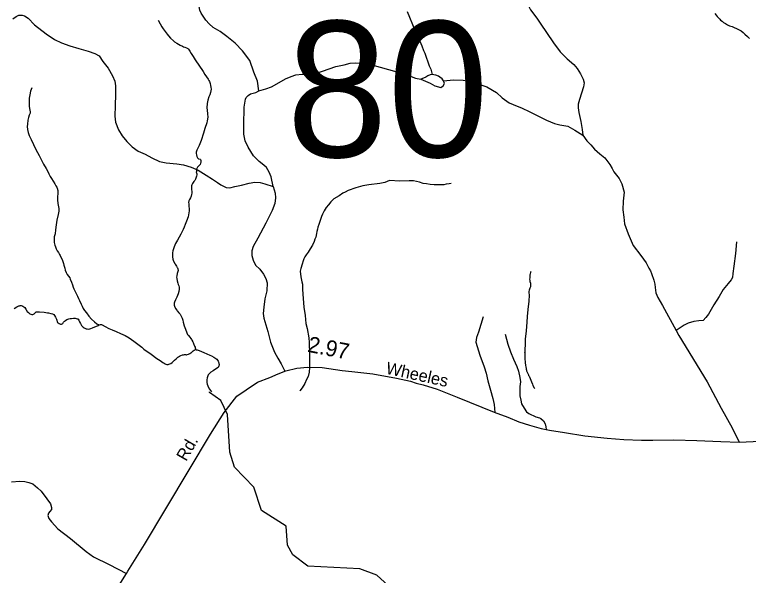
# Model space of a CAD drawing. Extents: x 2220236 to 2384410, y 720751 to 894131.
# Drawn here: x 2300357 to 2306111, y 864576 to 868976 of the extents above; entities that cross this region are included whole.
import ezdxf

# ---------------------------------------------------------------- set-up
doc = ezdxf.new("R2010")
doc.units = 0
doc.layers.add('Default', color=7, linetype='Continuous')

msp = doc.modelspace()

# ---------------------------------------------------------------- linework, layer by layer
at = {"layer": 'Default'}
for points in [[(2302271.3, 868378.4), (2302261.1, 868454.7), (2302233.2, 868525.8), (2302200.2, 868617.3), (2302144.3, 868693.6), (2302085.9, 868752), (2302019.8, 868805.4), (2301969, 868843.5), (2301913.2, 868876.6), (2301882.7, 868904.5), (2301857.3, 868932.5), (2301819.2, 868988.4), (2301809, 869011.3), (2301801.4, 869057)], [(2304370.5, 869077.3), (2304403.5, 869013.8), (2304451.8, 868947.7), (2304479.7, 868909.6), (2304583.8, 868754.6), (2304634.6, 868683.4), (2304690.5, 868630), (2304743.9, 868584.3), (2304769.3, 868553.8), (2304794.7, 868513.1), (2304815, 868469.9), (2304822.6, 868442), (2304817.5, 868408.9), (2304802.3, 868360.6), (2304787, 868309.8), (2304776.9, 868274.2), (2304776.9, 868246.3), (2304782, 868208.2), (2304797.2, 868137), (2304807.4, 868076), (2304812.4, 868030.2)], [(2303435.3, 869000.6), (2303494.8, 868855.2), (2303511.2, 868823.5), (2303550.1, 868731.8), (2303562.6, 868696.1), (2303572.7, 868674.1), (2303607.8, 868574.5), (2303620.1, 868548.6), (2303630.9, 868505.7)], [(2305848.6, 868984.5), (2305858.7, 868972.7), (2305866.7, 868962.4), (2305873.7, 868954.5), (2305886.8, 868941.1), (2305894.1, 868934), (2305905.3, 868924.6), (2305916.1, 868916), (2305931.3, 868906.7), (2305946.7, 868896.7), (2305964.8, 868888.4), (2305984.7, 868882.6), (2306000.7, 868876.7), (2306018.9, 868868.4), (2306038.7, 868858.6), (2306054.7, 868848.7), (2306070.8, 868836.2), (2306084.7, 868824.5), (2306104.8, 868806.3), (2306120.7, 868790.6)], [(2300343.5, 868942.6), (2300368.9, 868963), (2300389.2, 868973.1), (2300414.6, 868973.1), (2300434.9, 868968.1), (2300462.9, 868947.7), (2300511.1, 868896.9), (2300602.6, 868825.7), (2300668.6, 868782.5), (2300724.5, 868754.6), (2300790.5, 868731.7), (2300859.1, 868711.4), (2300932.8, 868691), (2300986.1, 868670.7), (2301019.1, 868652.9), (2301049.6, 868609.7), (2301090.2, 868556.3), (2301123.3, 868495.3), (2301143.6, 868454.7), (2301148.7, 868416.6), (2301148.7, 868350.5), (2301146.1, 868264.1), (2301143.6, 868180.2), (2301148.7, 868131.9), (2301171.5, 868073.5), (2301199.4, 868025.2), (2301237.5, 867982), (2301278.2, 867938.8), (2301326.4, 867905.7), (2301379.8, 867880.3), (2301433.1, 867852.3), (2301491.5, 867824.4), (2301544.9, 867814.2), (2301628.7, 867806.6), (2301682, 867799), (2301740.4, 867778.6), (2301796.3, 867755.8), (2301859.8, 867717.6), (2301908.1, 867684.6), (2301948.7, 867659.2), (2301974.1, 867641.4), (2302014.8, 867621.1), (2302045.2, 867618.5), (2302083.3, 867628.7), (2302136.7, 867638.9), (2302195.1, 867654.1), (2302240.8, 867661.7), (2302281.4, 867659.2), (2302319.5, 867649), (2302385.6, 867628.7)], [(2301481.5, 868934.2), (2301497.6, 868903.7), (2301511.6, 868879.7), (2301521.5, 868866.3), (2301529.6, 868855.8), (2301537.7, 868843.9), (2301553.6, 868822.4), (2301563.7, 868809.8), (2301579.6, 868792.2), (2301601.7, 868771.9), (2301611.6, 868764.1), (2301629.7, 868751.6), (2301641.6, 868743.9), (2301655.7, 868736.3), (2301673.7, 868728), (2301681.6, 868724.2), (2301691.6, 868720.6), (2301705.6, 868716.1), (2301715.6, 868710.2), (2301719.6, 868706.1), (2301725.7, 868698.2), (2301731.7, 868690.2), (2301741.6, 868671.8), (2301755.6, 868647.8), (2301773.7, 868622.1), (2301835.6, 868530.4), (2301849.6, 868508), (2301861.6, 868487.8), (2301873.7, 868470.3), (2301879.6, 868458.4), (2301883.7, 868451.9), (2301889.7, 868435.8), (2301893.8, 868419.5), (2301896.3, 868408), (2301897.8, 868391.7), (2301895.7, 868377.8), (2301893.6, 868366.1), (2301887.6, 868346.3), (2301879.7, 868330.3), (2301871.7, 868306.2), (2301867.6, 868278.2), (2301865.1, 868246.1), (2301867.5, 868227.2), (2301869.7, 868197.9), (2301871.6, 868171.5), (2301867.6, 868142), (2301863.6, 868126.2), (2301849.6, 868082.2), (2301837.7, 868046.3), (2301819.4, 867989.7), (2301803.6, 867949.7), (2301793.7, 867929.6), (2301787.5, 867918), (2301785.6, 867912.1), (2301781.6, 867897.9), (2301781, 867888.1), (2301781.7, 867875.7), (2301785.6, 867863.7), (2301791.6, 867854.1), (2301794.1, 867850.8), (2301799.5, 867846.2), (2301811.7, 867841.7), (2301814.8, 867838.7), (2301817.7, 867832.2), (2301817.6, 867824), (2301817.2, 867815), (2301815.6, 867809.9), (2301811.5, 867801.5), (2301805.6, 867795.5), (2301797.7, 867787.9), (2301791.6, 867780.3), (2301785.1, 867768.4), (2301783.7, 867763.6), (2301782, 867754.3), (2301781.7, 867743.7), (2301781.6, 867739.7), (2301785.6, 867727.4), (2301785.6, 867721.6), (2301785.7, 867720), (2301783.6, 867707.7), (2301781.6, 867701.9), (2301775, 867686), (2301769.7, 867675.9), (2301763, 867666.7), (2301757.5, 867659.8), (2301751.5, 867650.6), (2301747.6, 867642.2), (2301744.4, 867632.3), (2301743.2, 867618.2), (2301743.6, 867603.5), (2301745.7, 867587.9), (2301745.6, 867575.7), (2301744.4, 867564.1), (2301741.2, 867550.9), (2301736.6, 867539.9), (2301727.2, 867525.7), (2301723.2, 867515.6)], [(2302271.3, 868378.4), (2302327.2, 868393.7), (2302370.3, 868408.9), (2302413.5, 868434.3), (2302482.1, 868472.5), (2302525.3, 868490.3), (2302563.4, 868503), (2302611.6, 868510.6), (2302667.5, 868510.6), (2302700.5, 868513.1), (2302731, 868520.8), (2302771.6, 868533.5), (2302875.8, 868569), (2302941.8, 868581.8), (2302987.5, 868594.5), (2303030.7, 868599.5), (2303076.4, 868594.5), (2303139.9, 868586.8), (2303223.7, 868564), (2303419.3, 868510.6), (2303500.6, 868477.5), (2303543.8, 868469.9)], [(2303630.9, 868505.7), (2303615.2, 868502.9), (2303598.6, 868495.6), (2303582.1, 868485.9), (2303562.8, 868477.5), (2303543.8, 868469.9)], [(2303543.8, 868469.9), (2303614.9, 868439.4), (2303653, 868416.6), (2303698.7, 868403.8), (2303719, 868419.1), (2303729.2, 868436.9), (2303721.6, 868457.2)], [(2303721.6, 868457.2), (2303709.9, 868471.8), (2303692.2, 868486.3), (2303680.1, 868493.6), (2303660.7, 868500.5), (2303645.4, 868504.9), (2303630.9, 868505.7)], [(2303721.6, 868457.2), (2303797.7, 868464.8), (2303874.9, 868461.4), (2303903, 868455.8), (2303997.3, 868430.8), (2304059.3, 868409.6), (2304135.8, 868366.3), (2304180.3, 868324.9), (2304236.7, 868285.4), (2304298.9, 868258.1), (2304331.2, 868246.4), (2304397.3, 868213.1), (2304528, 868147.2), (2304591.5, 868121.7), (2304632.1, 868111.6), (2304695.6, 868101.4), (2304751.5, 868070.9), (2304812.4, 868030.2)], [(2300490.4, 868402.2), (2300481.2, 868375.6), (2300475.4, 868348.2), (2300471.3, 868321.8), (2300469.3, 868310.3), (2300469.4, 868279.9), (2300469.3, 868267.5), (2300469.3, 868257.7), (2300472.4, 868239.8), (2300476.6, 868226.8), (2300479.1, 868213.9), (2300477.4, 868202.2), (2300471.3, 868188.1), (2300466.2, 868168.1), (2300461.2, 868147.5), (2300457.2, 868117.7), (2300455.2, 868098), (2300457.3, 868075.9), (2300463.3, 868051.5), (2300471.3, 868028.1), (2300485.4, 867997.4), (2300505.2, 867958), (2300523.2, 867917.7), (2300549.3, 867872), (2300569.3, 867829.4), (2300583.2, 867802), (2300603.3, 867770), (2300618.8, 867740.4), (2300625.3, 867727.5), (2300635.3, 867707.3), (2300645.4, 867691.3), (2300659.3, 867669.8), (2300671.3, 867649.7), (2300680.6, 867633.7), (2300687.2, 867621.7), (2300691.4, 867613.7), (2300695.3, 867595.7), (2300695.4, 867569.5), (2300693.4, 867549.8), (2300691.8, 867524.3), (2300695.3, 867494), (2300699.2, 867481.8), (2300704.1, 867454.2), (2300703.4, 867433.5), (2300697.2, 867407.9), (2300687.2, 867364), (2300681.3, 867327.8), (2300677.3, 867287.4), (2300673.2, 867256), (2300667.4, 867233.6), (2300667.3, 867219.6), (2300667.3, 867205.8), (2300667.2, 867197.6), (2300667.2, 867187.6), (2300669.2, 867177.8), (2300671.7, 867167.3), (2300677.2, 867153.6), (2300683.2, 867139.8), (2300691.3, 867123.7), (2300699.3, 867109.4), (2300707.5, 867095), (2300713.3, 867085.2), (2300719.3, 867074), (2300729.3, 867055.6), (2300735.3, 867039.5), (2300739.2, 867024), (2300743.2, 867009.4), (2300749.3, 866985.8), (2300753.3, 866971.2), (2300761.3, 866951.9), (2300769.3, 866937.4), (2300779.3, 866923.8), (2300788.2, 866911.2), (2300793.1, 866899.8), (2300803.2, 866877.2), (2300811.3, 866855.5), (2300816.2, 866838.5), (2300821.3, 866825.5), (2300829.2, 866809.4), (2300837.3, 866793.4), (2300849.3, 866767.6), (2300857.7, 866748.2), (2300865.3, 866733.7), (2300879.3, 866705.7), (2300885.3, 866689.5), (2300895.2, 866669.3), (2300905.3, 866655.9), (2300919.2, 866635.9), (2300939.2, 866609.7), (2300959.4, 866587.5), (2300982.7, 866565.4), (2301002.3, 866550.6), (2301018.3, 866541.5)], [(2302385.6, 867628.7), (2302367.8, 867702.4), (2302352.6, 867740.5), (2302332.2, 867776.1), (2302311.9, 867796.4), (2302273.8, 867824.4), (2302230.6, 867867.6), (2302187.5, 867936.2), (2302164.6, 867987), (2302154.4, 868037.9), (2302154.4, 868109), (2302157, 868251.4), (2302167.1, 868312.4), (2302172.2, 868327.6), (2302187.5, 868342.8), (2302207.8, 868355.6), (2302248.4, 868365.7), (2302271.3, 868378.4)], [(2304812.4, 868030.2), (2304844.2, 867987), (2304874.7, 867954), (2304905.1, 867921), (2304945.8, 867885.4), (2304985.1, 867853.7), (2305024.5, 867801.5), (2305042.3, 867768.5), (2305057.5, 867743.1), (2305098.2, 867689.7), (2305118.5, 867649), (2305136.3, 867582.9), (2305128.6, 867511.8), (2305126.1, 867445.7), (2305133.7, 867387.2), (2305141.3, 867333.9), (2305168, 867255.1), (2305208.7, 867166.1), (2305267.1, 867087.3), (2305310.2, 867028.9), (2305331.9, 866986.6), (2305344.1, 866966.7), (2305352.8, 866944), (2305369.2, 866894), (2305377.6, 866862.1), (2305379.8, 866836.2), (2305386.3, 866794.3), (2305392.6, 866774.3), (2305400.7, 866756.5), (2305439.3, 866693), (2305545.6, 866498.3)], [(2303780.1, 867650.2), (2303766, 867647.8), (2303740.1, 867645.9), (2303722, 867642), (2303708, 867642.2), (2303670.1, 867639.8), (2303646.1, 867639.7), (2303616.1, 867644.2), (2303586.1, 867647.8), (2303560, 867651.7), (2303531.9, 867662), (2303508, 867666), (2303483.9, 867672.4), (2303450.1, 867671.8), (2303378, 867669.7), (2303296, 867673.7), (2303259.9, 867659.8), (2303222, 867651.9), (2303135.9, 867640.1), (2303088, 867632.4), (2303033.9, 867617.8), (2302973.8, 867595.7), (2302947.9, 867584), (2302929.9, 867574.3), (2302901.8, 867555.7), (2302859.9, 867530.2), (2302835.8, 867506.4), (2302817.7, 867484.2), (2302799.8, 867463.9), (2302783.8, 867437.6), (2302771.8, 867410.1), (2302763.7, 867391.8), (2302757.8, 867375.9), (2302749.8, 867354.2), (2302741.8, 867330.1), (2302735.7, 867307.8), (2302731.8, 867292), (2302727.7, 867273.9), (2302723.8, 867258.1), (2302717.9, 867231.4), (2302711.8, 867214), (2302705.7, 867195.7), (2302691.6, 867168.1), (2302675.8, 867139.5), (2302659.7, 867113.4), (2302643.8, 867091.5), (2302631.8, 867076.3), (2302625.7, 867059.6), (2302619.7, 867043.7), (2302611.8, 867018), (2302601.8, 866983.8), (2302595.8, 866963.9), (2302601.8, 866920), (2302609.6, 866880.1), (2302613.8, 866862), (2302613.8, 866821.8), (2302615.8, 866783.5), (2302619.8, 866750), (2302625.8, 866682), (2302635.7, 866616), (2302639.8, 866553.8), (2302651.7, 866514), (2302663.6, 866441.5), (2302667.8, 866404.1), (2302667.7, 866376), (2302669.7, 866341.7), (2302669.7, 866308.1), (2302669.6, 866276.1), (2302669.6, 866231.9), (2302669.6, 866208.1), (2302667.7, 866171.8), (2302657.7, 866137.7), (2302645.7, 866113.4), (2302631.8, 866081.7), (2302611.5, 866048), (2302593.7, 866023.5), (2302593.3, 866023.5)], [(2302385.6, 867628.7), (2302400.8, 867575.3), (2302403.4, 867539.7), (2302398.3, 867494), (2302375.4, 867440.6), (2302327.2, 867339), (2302263.7, 867222), (2302228.1, 867156), (2302217.9, 867122.9), (2302217.9, 867087.3), (2302228.1, 867049.2), (2302245.9, 867011.1), (2302278.9, 866978.1), (2302309.4, 866939.9), (2302327.2, 866906.9), (2302337.3, 866871.3), (2302334.8, 866807.8), (2302319.5, 866746.8), (2302311.9, 866680.7), (2302306.8, 866632.4), (2302311.9, 866594.3), (2302343.7, 866490.1), (2302364, 866406.2), (2302394.5, 866327.4), (2302419.9, 866281.7), (2302448, 866236.9), (2302475.7, 866177.6)], [(2301723.2, 867515.6), (2301721.1, 867503.3), (2301721.6, 867491.7), (2301723.5, 867473.8), (2301726, 867451.9), (2301725.6, 867437.8), (2301717.6, 867389.9), (2301704.2, 867354.9), (2301695, 867329.9), (2301685.4, 867309.7), (2301677.5, 867289.8), (2301670.1, 867273.9), (2301660.1, 867254.7), (2301633.4, 867207.6), (2301617.5, 867181.5), (2301607.2, 867154.9), (2301597.4, 867124.1), (2301595.5, 867107.6), (2301595, 867099.4), (2301595.5, 867082.2), (2301596, 867074.8), (2301597.5, 867057.6), (2301599.5, 867049.5), (2301603.6, 867041.5), (2301613.1, 867024.5), (2301616.7, 867019), (2301626.6, 867002.2), (2301629.4, 866997.3), (2301631.8, 866993.4), (2301633.5, 866990.1), (2301635.6, 866982.8), (2301638.8, 866968.1), (2301637.4, 866959.8), (2301631.5, 866945.8), (2301627.5, 866927.4), (2301626.9, 866916.8), (2301627.6, 866905.4), (2301631, 866886.5), (2301635.5, 866869.5), (2301639.4, 866857.5), (2301643.5, 866849.4), (2301646.6, 866837.2), (2301647.6, 866823.4), (2301644.4, 866802.7), (2301639.5, 866786.1), (2301629.6, 866759.4), (2301619.5, 866737.6), (2301611.4, 866720.1), (2301608.9, 866711.8), (2301607.5, 866703.5), (2301607.8, 866696.1), (2301609.5, 866688), (2301619.5, 866669.6), (2301627.6, 866657.5), (2301632.4, 866651.1), (2301645.4, 866636), (2301654, 866626.6), (2301663.5, 866611.4), (2301670.5, 866595.2), (2301675.6, 866579.8), (2301679.4, 866563.6), (2301687.4, 866535.3), (2301691.4, 866521.5), (2301695.9, 866508.7), (2301698.8, 866500.4), (2301703.6, 866487.6), (2301706.5, 866479.5), (2301713.4, 866467.4), (2301719.4, 866457.8), (2301729.5, 866446), (2301737.5, 866435.5), (2301743.4, 866427.6), (2301747.3, 866421.1), (2301753.6, 866410), (2301757.1, 866402.7), (2301760.2, 866394.6), (2301767.6, 866375.3), (2301771.6, 866365.7), (2301773.6, 866359.2), (2301774.8, 866355.8), (2301775.5, 866347.7)], [(2306019.7, 867194), (2306011.2, 867102.5), (2305997.7, 867002.5), (2305990.9, 866944.9), (2305987.5, 866914.4), (2305975.7, 866895.8), (2305953.6, 866867), (2305914.7, 866819.6), (2305882.5, 866763.6), (2305840.2, 866699.3), (2305797.9, 866624.7), (2305777.5, 866599.3), (2305757.2, 866575.6), (2305723.4, 866573.9), (2305682.7, 866568.8), (2305638.7, 866555.2), (2305609.3, 866540.9), (2305575.4, 866518.9), (2305545.6, 866498.3)], [(2304406.3, 866960.2), (2304402.1, 866954.4), (2304400.1, 866940.3), (2304398.1, 866933.6), (2304396.2, 866923.7), (2304396.2, 866912.3), (2304396.1, 866899.9), (2304398.1, 866890.2), (2304398.2, 866883.6), (2304402.2, 866869.8), (2304402.2, 866858.4), (2304402.2, 866850.1), (2304402.2, 866840.3), (2304398.2, 866830.2), (2304394.1, 866821.8), (2304392.3, 866813.5), (2304390.3, 866803.6), (2304390.2, 866796.2), (2304392.1, 866774.3), (2304390.2, 866728.2), (2304382.1, 866662.2), (2304376.1, 866607.8), (2304374.1, 866564.3), (2304368.2, 866494.2), (2304362.2, 866429.9), (2304360.1, 866397.8), (2304358.1, 866339.5), (2304358.2, 866321.5), (2304358.1, 866323.9), (2304358, 866278.1), (2304360.1, 866247.8), (2304364, 866224.1), (2304366.1, 866211.8), (2304368, 866199.7), (2304368.2, 866195.5), (2304370.1, 866187.4), (2304372.2, 866181.8), (2304378.2, 866165.7), (2304386.1, 866149.6), (2304388.1, 866145.5), (2304392.1, 866139.8), (2304396.1, 866133.6), (2304400, 866122.2), (2304410.2, 866094), (2304418, 866077.9), (2304422.1, 866065.6), (2304432.1, 866048), (2304435.3, 866043.2)], [(2300353.1, 866671.7), (2300373.4, 866682.5), (2300384.2, 866687.7), (2300389.3, 866690.6), (2300394, 866692.4), (2300399.2, 866693.4), (2300408.4, 866692.9), (2300415.1, 866691.6), (2300421.8, 866689.3), (2300429.2, 866683.8), (2300435.3, 866677.6), (2300443.2, 866664), (2300455.1, 866647.2), (2300464.1, 866637.8), (2300475.3, 866629.3), (2300484.8, 866624.7), (2300490.7, 866623.3), (2300495.1, 866623.5), (2300498.9, 866623.6), (2300504, 866625.4), (2300508.9, 866628), (2300513.2, 866631.6), (2300521.3, 866639.3), (2300525.1, 866643.5), (2300528.2, 866645.2), (2300533.2, 866645.4), (2300551.3, 866644.6), (2300587.2, 866642.1), (2300613.2, 866637.3), (2300622.1, 866635.3), (2300640.8, 866631), (2300652.6, 866628.3), (2300662.8, 866622.1)], [(2300662.8, 866622.1), (2300669.3, 866615.8), (2300676.6, 866603.7), (2300684.3, 866586.8), (2300687.2, 866577.9), (2300691.1, 866565.9), (2300693.1, 866561.8), (2300697.3, 866557.9), (2300707.1, 866551.7), (2300716.3, 866548.7), (2300725.3, 866547.5), (2300729.2, 866549.2), (2300733.3, 866553.6), (2300739.3, 866562.9), (2300747.1, 866571.4), (2300755.3, 866577.5), (2300765.2, 866583.5), (2300772.7, 866586.4), (2300780.4, 866589.2), (2300790.9, 866592), (2300801.3, 866593.2), (2300818.2, 866594.9), (2300831, 866594.4), (2300839.7, 866593.2), (2300846.6, 866590.3), (2300851.1, 866588.9), (2300855.2, 866585.6), (2300861.1, 866577.7), (2300866.4, 866566.5), (2300873.2, 866551.9), (2300880.1, 866538.2), (2300889.8, 866528), (2300894.3, 866524), (2300902.8, 866517.9), (2300911.2, 866513.3), (2300917.7, 866511.1), (2300924.9, 866509.8), (2300935, 866509.3), (2300946.7, 866510.7), (2300955.4, 866513.5), (2300968.4, 866518), (2300985.3, 866525.3), (2301005.3, 866535.2), (2301011.2, 866538), (2301018.3, 866541.5)], [(2304031.4, 866604.5), (2303995.9, 866485), (2303978.1, 866441.8), (2303973, 866406.2), (2304006, 866304.6), (2304039, 866213.1), (2304054.3, 866162.2), (2304068.5, 866103.7), (2304078.4, 866065.5), (2304088.4, 866030.6), (2304106.6, 865964.2), (2304116.6, 865916), (2304122.7, 865854.9)], [(2301018.3, 866541.5), (2301023.4, 866543.3), (2301030.4, 866544.4), (2301037, 866543.9), (2301043.3, 866541.7), (2301067.2, 866527.9), (2301094.2, 866514.2), (2301121.3, 866503.9), (2301153.4, 866491.2), (2301187.2, 866475.4), (2301223.3, 866459.7), (2301255.3, 866439.6), (2301291.4, 866413.2), (2301353.8, 866365.8), (2301370.2, 866352.4), (2301427.5, 866311.4), (2301471.5, 866277.8), (2301497.3, 866261.6), (2301507.4, 866255.4), (2301519.3, 866247.7), (2301529.4, 866241.5), (2301538.4, 866236.3), (2301543.5, 866233.9), (2301551.4, 866231.8), (2301561.4, 866231.4), (2301566.8, 866232.4), (2301573.5, 866235.1), (2301580.9, 866238.8), (2301591.4, 866247.5), (2301599.5, 866253.6), (2301611.5, 866263.9), (2301623.4, 866275.8), (2301637.3, 866288), (2301641.4, 866291.3), (2301649.8, 866296.7), (2301661.4, 866302), (2301673.4, 866305.8), (2301681.1, 866307.8), (2301689.4, 866309.7), (2301697.5, 866309.2), (2301701.5, 866307.8), (2301705.1, 866308), (2301709.1, 866308.9), (2301719.5, 866313.3), (2301731.5, 866318), (2301737.4, 866321.5), (2301743.4, 866325.9), (2301757.5, 866337.9), (2301765.5, 866344), (2301770.2, 866346.6), (2301775.5, 866347.7)], [(2304202.8, 866468.8), (2304224.8, 866390.9), (2304245.1, 866329.9), (2304270.5, 866272.3), (2304295.9, 866216.4), (2304307.8, 866177.4), (2304319.6, 866128.3), (2304323, 866094.4), (2304318, 866058.8), (2304318, 866026.6), (2304319.6, 865984.3), (2304328.1, 865952.1), (2304333.2, 865923.3), (2304351.8, 865889.4), (2304372.1, 865860.6), (2304390.8, 865847), (2304444.9, 865819.9), (2304473.7, 865813.1), (2304483.9, 865806.3), (2304504.2, 865787.7), (2304517.8, 865765.7), (2304522.8, 865742), (2304526.6, 865721.2)], [(2305545.6, 866498.3), (2305566.8, 866459.6), (2305789.6, 866095.4), (2305899.1, 865889.5), (2305985.4, 865733.4), (2306039.4, 865620.4)], [(2301775.5, 866347.7), (2301781.1, 866347.1), (2301787.4, 866345.7), (2301803.5, 866339.8), (2301839.4, 866325.7), (2301887.4, 866303.8), (2301901.6, 866298), (2301919.4, 866287.9), (2301941.5, 866271.6), (2301946.7, 866266), (2301953.5, 866257.3), (2301955.5, 866251.8), (2301959.4, 866239.6), (2301961.6, 866231.4), (2301961, 866226.4), (2301959.4, 866219.9), (2301956.3, 866212.4), (2301953.5, 866207.3), (2301931.5, 866193.2), (2301912.6, 866181), (2301895.5, 866169.7), (2301885.4, 866161.1), (2301875.5, 866149.9), (2301871.4, 866141.5), (2301865.4, 866127.4), (2301863.4, 866111.8), (2301863.5, 866099.4), (2301864.5, 866089.6), (2301867.4, 866077.5), (2301871.4, 866063.7), (2301875.5, 866055.6), (2301885.5, 866038), (2301893.5, 866027.6), (2301901.8, 866015.7)], [(2301111.2, 864393.5), (2301234, 864591.9), (2301244.9, 864609.4), (2301375.5, 864817.6), (2301891.9, 865685.1), (2302000.7, 865854.4), (2302098.6, 865981.8), (2302172.2, 866032.6), (2302261.1, 866091.1), (2302357.3, 866129.6), (2302423.8, 866156.8), (2302484.2, 866181), (2302568.9, 866202.1), (2302653.5, 866211.2), (2302768.3, 866208.2), (2302925.5, 866184), (2303001, 866174.9), (2303167.2, 866156.8), (2303351.6, 866123.5), (2303460.4, 866099.3), (2303505.7, 866085.7), (2303560.1, 866070.6), (2303671.9, 866037.4), (2303826.3, 865974.8), (2304118.4, 865856.7), (2304226.1, 865816.4), (2304312.4, 865781.5), (2304393.8, 865754.9), (2304486.7, 865728.4), (2304526.6, 865721.2), (2304551.4, 865716.7), (2304669.3, 865696.8), (2304829.4, 865671.5), (2305004.7, 865653.4), (2305134.6, 865641.3), (2305273.7, 865638.3), (2305361.3, 865638.3), (2305527.2, 865640.9), (2305708.3, 865633.7), (2305895.8, 865627.1), (2306039.4, 865620.4), (2306869.2, 865661.9)], [(2301884.5, 866011.1), (2301884.1, 866015.2)], [(2303315.8, 864471.4), (2303197.6, 864578.1), (2303063.7, 864628.4), (2302655.7, 864647.8), (2302537.8, 864738.1), (2302495.7, 864811.9), (2302485.7, 864962.5), (2302292.7, 865085.8), (2302232.7, 865267.2), (2302080.7, 865425.1), (2302045.6, 865541.8), (2302026.6, 865839.6), (2301974.7, 865949.1), (2301884.5, 866011.1)], [(2300332.7, 865310.7), (2300397.4, 865315.7), (2300435.6, 865314), (2300467.1, 865305.7), (2300498.7, 865294.1), (2300535.2, 865264.2), (2300563.4, 865236), (2300608.2, 865176.2), (2300638.1, 865136.3), (2300646.4, 865109.7), (2300644.7, 865093.1), (2300633.1, 865078.2), (2300621.5, 865064.9), (2300618.2, 865045), (2300624.8, 865021.7), (2300644.7, 864996.8), (2300696.2, 864942), (2300795.8, 864865.6), (2300916.9, 864762.6), (2300974.2, 864722.8), (2301098.7, 864661.3), (2301234, 864591.9)]]:
    msp.add_lwpolyline(points, dxfattribs=at)

# ---------------------------------------------------------------- texts
msp.add_text('80', height=1066.27, dxfattribs=at).set_placement((2302489, 867859.2))
for s, height, rotation, p in [('2.97', 125, 348.90114, (2302648.2, 866331.6)), ('Wheeles', 95, 347.61546, (2303262.8, 866159.8)), ('Rd.', 95, 60.04772, (2301701.5, 865465.5))]:
    msp.add_text(s, height=height, rotation=rotation, dxfattribs=at).set_placement(p)

doc.saveas('drawing.dxf')
